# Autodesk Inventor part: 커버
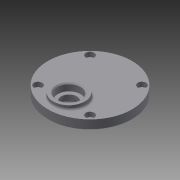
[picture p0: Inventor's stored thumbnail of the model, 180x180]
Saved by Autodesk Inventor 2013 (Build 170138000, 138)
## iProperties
Created: 2015-07
Part Number: 커버
Material: 일반
Document SubType Name: Modeling
Designer: user
Density: 1 g/cm^3
Author: user
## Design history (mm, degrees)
sketch "스케치1"
  geometry: C1 r 40 at (0, 0); 1 further point
  constraints: 1 centre point, 1 coincident
  dimensions: "d0" = 80 diameter of C1
extrude "돌출1" new body sketch "스케치1" distance "d1" = 9; taper "d2" = 0 deg
sketch "스케치2"
  geometry: L1 (0, 0)-(0, -20); C1 r 40 at (0, 0) reference; C2 r 15 at (0, -20)
  constraints: 2 end point, 1 centre point, 1 coincident, 1 vertical
  dimensions: "d4" = 20 distance of L1.start L1.end; "d5" = 30 diameter of C2
extrude "돌출2" join sketch "스케치2" distance "d6" = 4; taper "d7" = 0 deg
node "작업 평면1"
sketch "스케치6"
  geometry: C1 r 15 at (0, 0) reference; 1 further point
hole "구멍3" sketch "스케치6" at (0, 0) diameter "d28" = 15; stored, may be unused: countersink angle "d32" = 90 deg, drill point angle "d34" = 0 deg; dims "d29" = 6, "d30" = 22, "d31" = 7, "d33" = 9
sketch "스케치7"
  geometry: L1 (0, 0)-(24.749, 24.749); L2 (0, 0)-(35, 0); C1 r 40 at (0, 0) reference; A1 r 35 centre (0, 0) between (24.749, 24.749) and (24.749, 24.749); 3 further points
  constraints: 4 end point, 2 point on circle, 1 centre point, 1 coincident, 1 equal length, 1 horizontal, 5 other
  dimensions: "d35" = 70 diameter of A1; "d36" = 45 deg angle of L2 L1; "d39" = 360 deg dimension on L1.start A1.end (derived)
hole "구멍4" sketch "스케치7" at (24.749, 24.749), (-24.749, 24.749), (-24.749, -24.749), (24.749, -24.749) diameter "d41" = 4.5; stored, may be unused: countersink angle "d45" = 90 deg, drill point angle "d47" = 0 deg; dims "d42" = 6, "d43" = 8, "d44" = 4.4, "d46" = 9
chamfer "모따기1" distance "d48" = 1; stored, may be unused: second distance "d49" = 2, angle "d50" = 45 deg
sketch "스케치8"
  geometry: L1 (0, 0)-(0, 11); L2 (0, 0)-(0, -20); C1 r 39 at (0, 0) reference; C2 r 14 at (0, 11); C3 r 14 at (0, -20)
  constraints: 4 end point, 2 centre point, 2 coincident, 1 collinear, 1 vertical
  dimensions: "d51" = 11 distance of L1.start L1.end; "d52" = 20 distance of L1.start L2.end; "d53" = 28 diameter of C2; "d54" = 28 diameter of C3
extrude "돌출4" join sketch "스케치8" distance "d55" = 3; taper "d56" = 0 deg
sketch "스케치9"
  geometry: C1 r 14 at (0, 0) reference; 1 further point
hole "구멍5" sketch "스케치9" at (0, 0) diameter "d57" = 18; stored, may be unused: countersink angle "d61" = 90 deg, drill point angle "d63" = 0 deg; dims "d58" = 6, "d59" = 22, "d60" = 7, "d62" = 8
sketch "스케치10"
  geometry: C1 r 14 at (0, 0) reference; 1 further point
hole "구멍6" sketch "스케치10" at (0, 0) diameter "d64" = 15; stored, may be unused: countersink angle "d68" = 90 deg, drill point angle "d70" = 0 deg; dims "d65" = 6, "d66" = 22, "d67" = 7, "d69" = 9
fillet "모깎기2" dims "d71" = 2
fillet "모깎기3" dims "d72" = 2
fillet "모깎기4" dims "d73" = 2
fillet "모깎기5" dims "d74" = 0.3
chamfer "모따기2" distance "d75" = 1; stored, may be unused: second distance "d76" = 2, angle "d77" = 45 deg
node "솔리드1"
